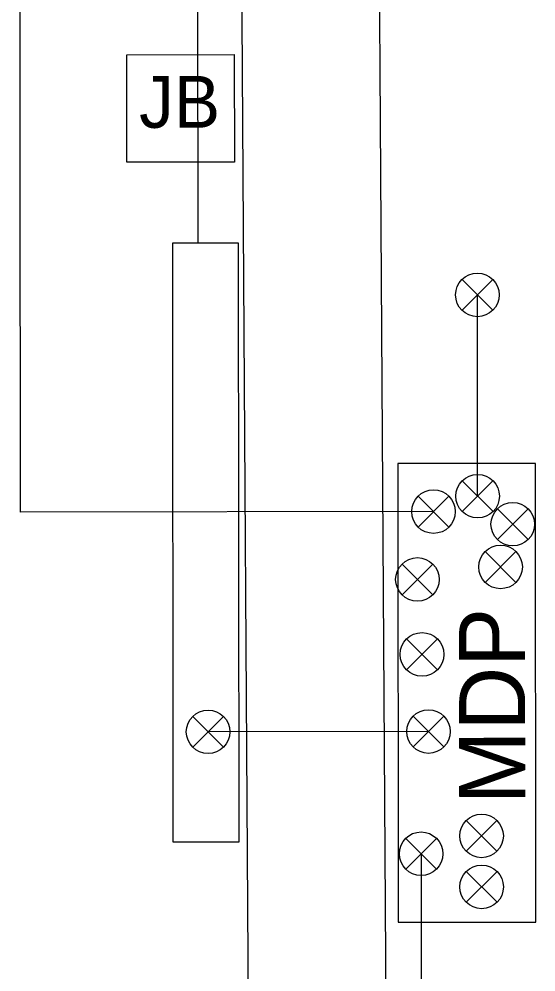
# Model space of a CAD drawing. Extents: x -2.6 to 16.3, y -2.7 to 7.5.
# Drawn here: x 4.312 to 5.251, y 2.776 to 4.508 of the extents above; entities that cross this region are included whole.
import ezdxf

# ---------------------------------------------------------------- set-up
doc = ezdxf.new("R2010")
doc.units = 0
doc.layers.add('HS_Concrete_Object', color=7, linetype='Continuous')
doc.layers.add('HS_Electrical_Devices', color=7, linetype='Continuous')

msp = doc.modelspace()

# ---------------------------------------------------------------- linework, layer by layer
at = {"layer": 'HS_Concrete_Object'}
for points in [[(4.7053, 6.2172), (4.7398, 0.8078)], [(4.9553, 6.2188), (4.9898, 0.8094)]]:
    msp.add_lwpolyline(points, dxfattribs=at)
at = {"layer": 'HS_Electrical_Devices'}
for p, q in [((4.6351, 5.3815), (4.6362, 4.1004)), ((5.1722, 3.9784), (5.1163, 4.0343)), ((5.1163, 3.9784), (5.1722, 4.0343)), ((5.1446, 3.6405), (5.1442, 4.0063)), ((5.1726, 3.6125), (5.1166, 3.6684)), ((5.1166, 3.6125), (5.1725, 3.6684)), ((5.0925, 3.5844), (5.0366, 3.6403)), ((5.0366, 3.5844), (5.0925, 3.6403)), ((5.2365, 3.5617), (5.1805, 3.6176)), ((5.1805, 3.5617), (5.2364, 3.6176)), ((5.2143, 3.4839), (5.1584, 3.5399)), ((5.1584, 3.4839), (5.2143, 3.5399)), ((5.0633, 3.4612), (5.0073, 3.5172)), ((5.0073, 3.4612), (5.0633, 3.5172)), ((5.0715, 3.325), (5.0156, 3.381)), ((5.0156, 3.325), (5.0715, 3.381)), ((4.683, 3.1844), (4.6271, 3.2403)), ((4.6271, 3.1844), (4.683, 3.2403)), ((5.0834, 3.1847), (5.0275, 3.2407)), ((5.0275, 3.1847), (5.0834, 3.2407)), ((5.0554, 3.2127), (4.655, 3.2123)), ((5.1798, 2.9952), (5.1239, 3.0511)), ((5.1239, 2.9952), (5.1798, 3.0511)), ((5.07, 2.9627), (5.0141, 3.0186)), ((5.0141, 2.9627), (5.07, 3.0186)), ((5.042, 2.9907), (5.0427, 2.3139)), ((5.1799, 2.9024), (5.124, 2.9584)), ((5.124, 2.9024), (5.1799, 2.9584))]:
    msp.add_line(p, q, dxfattribs=at)
msp.add_lwpolyline([(5.0645, 3.6124), (4.3141, 3.6117), (4.3116, 6.3146)], dxfattribs=at)
for points in [[(4.5072, 4.4427), (4.7025, 4.4429), (4.7027, 4.2476), (4.5073, 4.2474)], [(4.7102, 4.1005), (4.5901, 4.1004), (4.5911, 3.0124), (4.7112, 3.0125)], [(5.2505, 2.8665), (5.2498, 3.6998), (4.9998, 3.6996), (5.0005, 2.8662)]]:
    msp.add_lwpolyline(points, close=True, dxfattribs=at)
for centre in [(5.1442, 4.0063), (5.1446, 3.6405), (5.0645, 3.6124), (5.2085, 3.5896), (5.1863, 3.5119), (5.0353, 3.4892), (5.0436, 3.353), (4.655, 3.2123), (5.0554, 3.2127), (5.1518, 3.0231), (5.042, 2.9907), (5.1519, 2.9304)]:
    msp.add_circle(centre, 0.0396, dxfattribs=at)

# ---------------------------------------------------------------- texts
for s, height, rotation, p in [('JB', 0.09437, 0.0523, (4.5297, 4.3099)), ('MDP', 0.12, 90.0523, (5.2311, 3.0809))]:
    msp.add_text(s, height=height, rotation=rotation, dxfattribs=at).set_placement(p)

doc.saveas('drawing.dxf')
